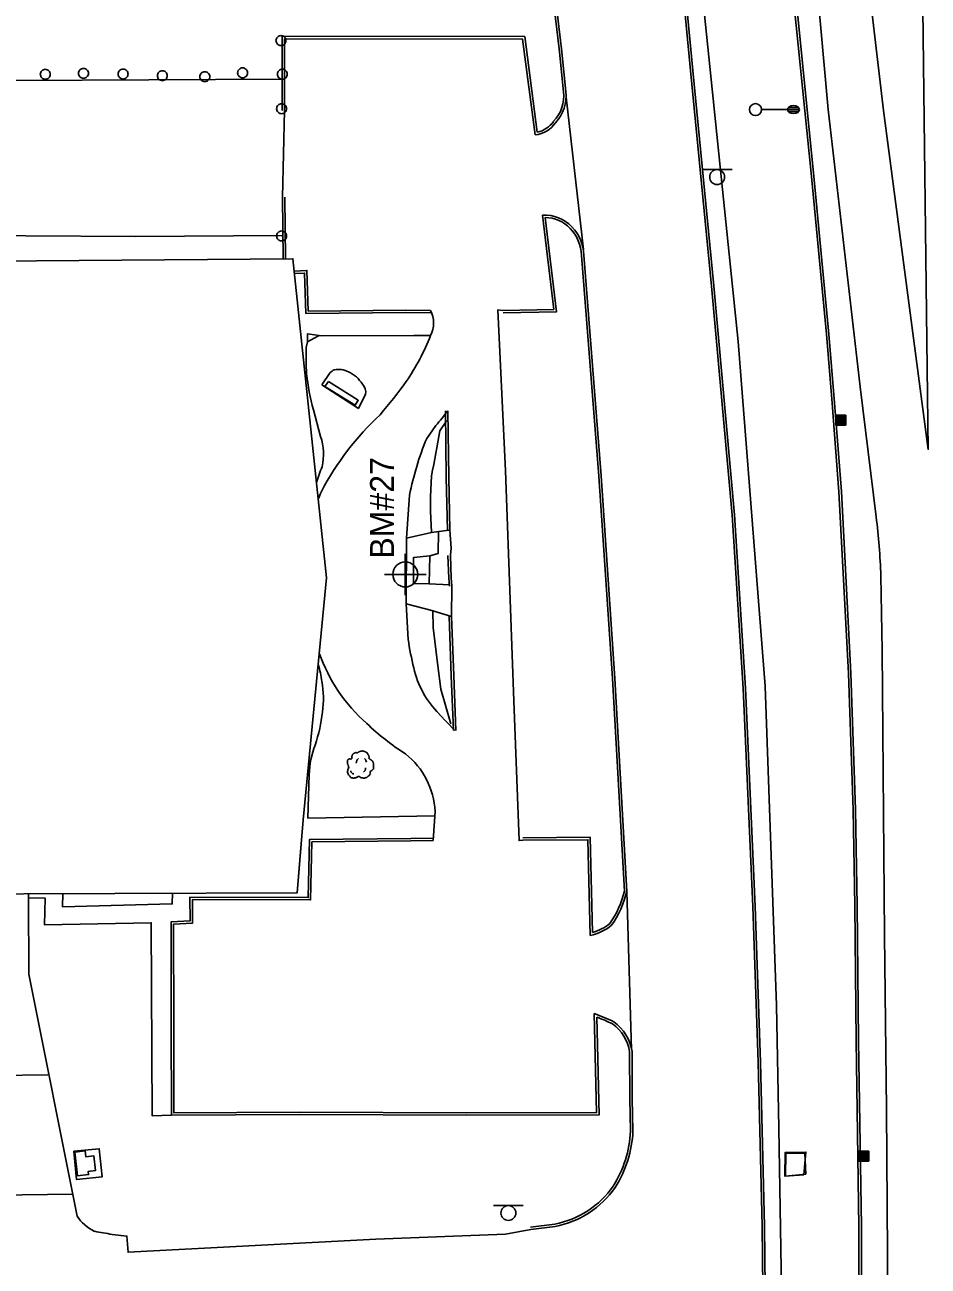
# Model space of a CAD drawing. Extents: x 2145380 to 2156929, y 139568 to 149130.
# Drawn here: x 2150561.8 to 2150788.1, y 141665.9 to 141976.9 of the extents above; entities that cross this region are included whole.
import ezdxf

# ---------------------------------------------------------------- set-up
doc = ezdxf.new("R2010")
doc.units = 0
for name, color, linetype in [('SURV_Benchmark', 7, 'Continuous'), ('SURV_Text', 7, 'Continuous'), ('TOPO_Asphalt', 7, 'Continuous'), ('TOPO_Building', 7, 'Continuous'), ('TOPO_Concrete', 7, 'Continuous'), ('TOPO_Curb Back', 7, 'Continuous'), ('TOPO_DRAIN_Manhole', 7, 'Continuous'), ('TOPO_Fence', 7, 'Continuous'), ('TOPO_Flowline', 7, 'Continuous'), ('TOPO_Light Pole', 7, 'Continuous'), ('TOPO_Misc', 7, 'Continuous'), ('TOPO_Misc Line', 7, 'Continuous'), ('TOPO_Sidewalk', 7, 'Continuous'), ('TOPO_Sign', 7, 'Continuous'), ('TOPO_Tree', 7, 'Continuous'), ('TOPO_Wall Freestanding', 7, 'Continuous')]:
    doc.layers.add(name, color=color, linetype=linetype)

# ---------------------------------------------------------------- blocks, each defined once
blk = doc.blocks.new('POST')
at = {"layer": 'TOPO_Misc'}
for start, end in [(89.99996, 180.00004), (179.99996, 270.00004), (359.99996, 90.00004), (269.99996, 0.00004)]:
    blk.add_arc((-0.01, 0.03), 3.16, start, end, dxfattribs=at)
blk = doc.blocks.new('CB')
at = {"layer": 'TOPO_Misc'}
for p, q in [((-3.08, 2.99), (3.24, 2.99)), ((-3.08, 2.68), (3.24, 2.68)), ((-3.08, 2.36), (3.24, 2.36)), ((-3.08, 2.05), (3.24, 2.05)), ((-3.08, 1.73), (3.24, 1.73)), ((-3.08, 1.4), (3.24, 1.4)), ((-3.08, 1.1), (3.24, 1.1)), ((-3.08, 0.77), (3.24, 0.77)), ((-3.08, 0.46), (3.24, 0.46)), ((-3.08, 0.14), (3.24, 0.14)), ((-3.08, -0.17), (3.24, -0.17)), ((-3.08, -0.48), (3.24, -0.48)), ((-3.08, -0.8), (3.24, -0.8)), ((-3.08, -1.11), (3.26, -1.11)), ((-3.08, -1.43), (3.26, -1.43)), ((-3.08, -1.75), (3.26, -1.75)), ((-3.08, -2.07), (3.26, -2.07)), ((-3.08, -2.39), (3.26, -2.39)), ((-3.08, -2.7), (3.26, -2.7)), ((-3.08, -3.02), (3.26, -3.02))]:
    blk.add_line(p, q, dxfattribs=at)
blk.add_lwpolyline([(3.26, -3.29), (3.24, 3.05), (-3.09, 3.04), (-3.08, -3.3), (3.26, -3.29)], dxfattribs=at)
blk = doc.blocks.new('LP')
at = {"layer": 'TOPO_Light Pole'}
blk.add_line((3.81, 0), (20.32, 0), dxfattribs=at)
for points in [[(20.32, 0), (27.94, 0)], [(20.32, 0), (23.5, 0)], [(20.83, 1.27), (27.43, 1.27)], [(20.83, 1.27), (23.5, 1.27)], [(23.71, 1.27), (27.43, 1.27)], [(23.71, 0), (27.94, 0)], [(20.83, -1.27), (27.43, -1.27)], [(20.83, -1.27), (23.5, -1.27)], [(23.71, -1.27), (27.43, -1.27)]]:
    blk.add_lwpolyline(points, dxfattribs=at)
blk.add_circle((0, 0), 3.81, dxfattribs=at)
blk.add_ellipse((24.13, 0), major_axis=(3.81, 0), ratio=0.666667, dxfattribs=at)
blk = doc.blocks.new('TREE')
at = {"layer": 'TOPO_Tree'}
for points in [[(-14.1, -0.4), (-14.2, 0.5), (-14.4, 1.4), (-14.6, 2.3), (-14.8, 3.2), (-15.5, 4), (-15.7, 4.9), (-15.8, 5.6), (-15.7, 6.3), (-15.7, 7), (-15.6, 7.9), (-15.7, 8.8), (-15.1, 9.7), (-14.6, 10.4), (-13.8, 10.5), (-13, 10.7), (-12.2, 11), (-11.1, 10), (-10.4, 10.7), (-9.4, 11.7), (-10.3, 13.3), (-9.8, 14.4), (-9.6, 15.1), (-9.3, 15.9), (-8.8, 16.5), (-8.2, 17.3), (-7.5, 17.7), (-6.7, 18.1), (-6.1, 18.4), (-5.6, 18.6), (-5.1, 18.7), (-4.5, 18.7), (-4, 18.5), (-3.5, 18.1)], [(-3.5, 17.6), (-3.1, 18.3), (-2.6, 18.8), (-1.9, 19.2), (-1, 19.7), (-0.2, 20), (0.7, 20.2), (1.6, 20.5), (2.5, 20.8), (3.4, 20.8), (4.1, 20.7), (4.8, 20.5), (5.5, 20.2), (6.4, 19.9), (7.3, 19.7), (8.2, 19.2), (9.4, 18.4), (10, 17.2), (10.8, 16), (11.2, 15.3), (11.6, 14.6), (11.9, 13.9), (12.2, 13.1), (11.4, 12), (11.9, 11.2), (12, 11), (12.2, 10.9), (12.4, 10.7), (12.9, 10.4), (13.5, 10), (14, 9.7), (14.7, 9.2), (15.4, 8.7), (16.1, 8.1), (16.7, 7.5), (16.9, 6.7), (17.1, 6), (17.6, 4.4), (17.7, 2.8), (17.7, 1.2), (17.7, -0.2), (17.8, -2.2), (16.6, -3), (15.5, -3.8), (14.3, -4.6), (13.2, -5.3)], [(13.2, -5.3), (13.3, -5.8), (13.4, -6.3), (13.4, -6.7), (13.8, -8.5), (12.2, -10), (10.8, -11.5), (10, -12.3), (9.1, -12.8), (8.2, -13.1), (6, -13.8), (3.3, -13.6), (1.3, -13.1), (0.5, -12.9), (-0.1, -11.4), (-0.8, -11.5), (-2, -11.6), (-3.3, -12.8), (-4.5, -13.1), (-6.1, -13.5), (-7.8, -14), (-9.3, -13.6), (-11.4, -13.1), (-12.8, -11.4), (-14.1, -9.4), (-15.3, -7.3), (-15.6, -5.1), (-15.1, -3), (-14.9, -1.9), (-13.9, -0.8), (-13.5, 0.1)], [(-4.2, 5.1), (-4.5, 6.1), (-4.3, 7.2), (-3.8, 8.2), (-3.3, 9.3), (-2.7, 10.3), (-1.6, 11)], [(5.9, 11.2), (6.5, 10.7), (7, 10.2), (7.4, 9.5), (7.9, 8.6), (8.3, 7.6), (8.5, 6.6)], [(-11.4, -4.5), (-11.5, -5.4), (-11, -6.3), (-10.1, -7.2), (-9.3, -8), (-8.5, -8.3), (-7.7, -8.1)], [(4.8, -6.3), (5.7, -5.7), (6.3, -4.9), (6.8, -3.9), (7.4, -2.8), (7.6, -1.7), (7.5, -0.6)]]:
    blk.add_open_spline(points, degree=3, dxfattribs=at)
blk = doc.blocks.new('BM')
at = {"layer": 'SURV_Benchmark'}
for p, q in [((0, 2.49), (0, 4.15)), ((-2.49, 0), (-4.16, 0)), ((4.16, 0), (2.49, 0)), ((0, -4.16), (0, -2.49))]:
    blk.add_line(p, q, dxfattribs=at)
for points in [[(0, 2.49), (0, 2.49), (0, 0), (2.49, 0), (2.49, 0), (2.49, 0)], [(0, 2.49), (0, 2.49), (0, 0), (2.49, 0), (2.49, 0), (2.49, 0), (2.49, 0)], [(-2.5, 0), (-2.49, 0), (0, 0), (0, -2.49), (0, -2.49)], [(-2.5, 0), (-2.49, 0), (0, 0), (0, -2.49), (0, -2.49)]]:
    blk.add_lwpolyline(points, dxfattribs=at)
for start, end in [(90.0638, 180.0068), (0.0638, 90.0068), (0.0638, 90.0068), (180.0638, 270.0068), (180.0638, 270.0068), (269.9472, 359.9927)]:
    blk.add_arc((0, 0), 2.5, start, end, dxfattribs=at)

msp = doc.modelspace()

# ---------------------------------------------------------------- linework, layer by layer
at = {"layer": 'TOPO_Asphalt'}
for p, q in [((2150701.7, 141920.59), (2150697.39, 141958.77)), ((2150626.34, 141933.73), (2150626.88, 141955.42)), ((2150668.68, 141828.57), (2150668.77, 141836.28)), ((2150713.8, 141720.23), (2150712.59, 141759.83)), ((2150573.84, 141683.97), (2150543.68, 141683.53))]:
    msp.add_line(p, q, dxfattribs=at)
for points in [[(2150784.22, 142321.18), (2150785.51, 142174.58), (2150786.21, 142060.54), (2150786.7, 141980.91), (2150787.83, 141890.92), (2150788.07, 141870.55), (2150776.91, 141955.43), (2150769.94, 142014.37), (2150769.64, 142016.94), (2150769.78, 142050.34), (2150769.37, 142062.64), (2150768.99, 142106.08), (2150768.6, 142191.81), (2150767.48, 142307.96)], [(2150775.04, 141853.65), (2150771.01, 141886.23), (2150762.99, 141955.69), (2150759.17, 141998.33), (2150755.55, 142020.63)], [(2150626.27, 141963.32), (2150559.5, 141962.96), (2150488.73, 141962.45), (2150479.24, 141962.33)], [(2150686.56, 141772.63), (2150685.62, 141772.54), (2150684.26, 141807.59), (2150682.22, 141865.21), (2150680.3, 141905.46), (2150681.57, 141905.37)], [(2150662.47, 141873.26), (2150664.77, 141876.51)], [(2150657.82, 141822.95), (2150657.36, 141831.85), (2150657.39, 141848.34), (2150658.17, 141859.11)], [(2150668.39, 141844.02), (2150668.63, 141845.8), (2150668.27, 141850.3)], [(2150754.12, 140985.36), (2150761.18, 141045.16), (2150767.3, 141118.3), (2150773.72, 141195.47), (2150779.3, 141269.82), (2150781.13, 141293.61), (2150780.7, 141357.79), (2150779.84, 141451.99), (2150779.07, 141536.53), (2150778.24, 141620.87), (2150777.64, 141705.29), (2150777.09, 141748.87), (2150776.58, 141820.16), (2150776.24, 141838.85)], [(2150669.48, 141800.11), (2150665.6, 141804.25)], [(2150664.56, 141779.85), (2150664.09, 141772.56)], [(2150583.67, 141673.9), (2150587.37, 141673.47), (2150587.68, 141669.42), (2150649.69, 141672.66), (2150682.21, 141673.95), (2150688.57, 141675.14)]]:
    msp.add_lwpolyline(points, dxfattribs=at)
for centre, radius, start, end in [((2150657.36, 141902.16), 6.82, 332.9628, 27.7838), ((2150606.79, 141921.5), 60.93, 326.0936, 338.3883), ((2150515.1, 141993.36), 177.32, 319.9381, 323.3492), ((2150699.13, 141827.05), 71.12, 132.797, 152.411), ((2150612.55, 141921.55), 68.96, 319.223, 323.1994), ((2150731.31, 141844.65), 74.55, 157.434, 168.8197), ((2150700.07, 141832.12), 69.78, 156.4643, 158.1438), ((2150592.67, 141831.49), 183.71, 2.297, 6.9274), ((2150733.88, 141834.22), 76.89, 188.4258, 193.8705), ((2150675.21, 141833.48), 42.06, 199.4563, 228.712), ((2150682.15, 141820.92), 23.48, 192.6406, 225.2177), ((2150691.99, 141848.44), 64.42, 226.2748, 237.2768), ((2150645.03, 141778.91), 19.55, 2.7398, 51.6264), ((2150583.94, 141684.33), 10.75, 212.8764, 244.2022), ((2150602.21, 141794.88), 122.39, 259.1945, 261.2879)]:
    msp.add_arc(centre, radius, start, end, dxfattribs=at)
at = {"layer": 'TOPO_Building'}
msp.add_lwpolyline([(2150414.75, 141916.64), (2150628.96, 141918.31), (2150637.38, 141838.37), (2150631.52, 141777.75), (2150630, 141759.43), (2150492.94, 141758.99), (2150492.91, 141755), (2150478.69, 141755.12), (2150478.72, 141759), (2150415.44, 141758.64), (2150415.72, 141792.35)], close=True, dxfattribs=at)
msp.add_lwpolyline([(2150478.58, 141759), (2150478.68, 141754.67), (2150493.03, 141755), (2150492.94, 141758.99), (2150630, 141759.43), (2150631.02, 141771.72)], dxfattribs=at)
at = {"layer": 'TOPO_Concrete'}
for points in [[(2150574.06, 141694.7), (2150580.43, 141695.35), (2150581.15, 141688.27), (2150574.78, 141687.63), (2150574.06, 141694.7)], [(2150756.95, 141688.82), (2150752.14, 141688.5), (2150752.24, 141694.4), (2150757.43, 141694.51), (2150756.95, 141688.82)]]:
    msp.add_lwpolyline(points, dxfattribs=at)
at = {"layer": 'TOPO_Curb Back'}
for p, q in [((2150626.34, 141933.73), (2150626.49, 141918.29)), ((2150626.94, 141933.73), (2150627.09, 141918.29))]:
    msp.add_line(p, q, dxfattribs=at)
for points in [[(2150665.92, 142234.23), (2150672.82, 142175.43), (2150683.05, 142079.24), (2150687.74, 142036.69), (2150695.66, 141970.85), (2150696.74, 141960.14)], [(2150666.52, 142234.29), (2150673.41, 142175.5), (2150683.64, 142079.3), (2150688.34, 142036.76), (2150696.26, 141970.91), (2150697.33, 141960.21)], [(2150745.49, 141717), (2150744.14, 141756.02), (2150741.71, 141810.65), (2150738.98, 141854.07), (2150733.82, 141911.47), (2150728.53, 141965.42), (2150722.71, 142026.7), (2150719.84, 142047.27)], [(2150746.09, 141717.02), (2150744.74, 141756.04), (2150742.31, 141810.69), (2150739.58, 141854.11), (2150734.42, 141911.53), (2150729.12, 141965.48), (2150723.31, 142026.77), (2150720.44, 142047.36)], [(2150752.87, 141998.18), (2150758.72, 141939.77), (2150762.6, 141899.37), (2150764.01, 141882.16), (2150765.73, 141859.91), (2150768.07, 141814.42), (2150769.27, 141780.28), (2150769.69, 141756.26), (2150770.02, 141722.4)], [(2150753.47, 141998.26), (2150759.31, 141939.83), (2150763.19, 141899.43), (2150764.61, 141882.21), (2150766.33, 141859.95), (2150768.67, 141814.45), (2150769.87, 141780.29), (2150770.29, 141756.27), (2150770.62, 141722.4)], [(2150690.16, 141950.01), (2150687.02, 141973.94), (2150626.27, 141974.02), (2150626.28, 141955.42)], [(2150689.65, 141949.31), (2150686.49, 141973.34), (2150626.87, 141973.42), (2150626.88, 141955.42)], [(2150681.57, 141905.37), (2150694.3, 141905.61), (2150691.47, 141929.18)], [(2150681.58, 141904.77), (2150694.98, 141905.03), (2150692.14, 141928.6)], [(2150701.25, 141919.15), (2150705.59, 141863.84), (2150709.02, 141813.11), (2150711.98, 141759.88)], [(2150701.85, 141919.19), (2150706.19, 141863.88), (2150709.62, 141813.15), (2150712.59, 141759.83)], [(2150629.29, 141915.18), (2150632.45, 141915.36), (2150632.78, 141905.18), (2150657.22, 141905.45), (2150663.4, 141905.34)], [(2150629.36, 141914.58), (2150631.87, 141914.72), (2150632.2, 141904.57), (2150657.22, 141904.85), (2150663.39, 141904.74)], [(2150667.17, 141880.24), (2150667.38, 141863.52), (2150667.67, 141850.29)], [(2150667.77, 141880.24), (2150667.98, 141863.53), (2150668.27, 141850.3)], [(2150667.79, 141843.98), (2150668.03, 141838.31), (2150668.17, 141836.24)], [(2150668.39, 141844), (2150668.63, 141838.34), (2150668.77, 141836.28)], [(2150668.08, 141828.68), (2150668.62, 141813.84), (2150669.18, 141800.1)], [(2150668.68, 141828.71), (2150669.22, 141813.87), (2150669.78, 141800.12)], [(2150705.04, 141728.32), (2150705.63, 141703.81), (2150672.4, 141703.76), (2150630.6, 141703.95), (2150598.53, 141703.74), (2150598.49, 141726.43), (2150598.43, 141752.15), (2150603.21, 141752.43), (2150603.17, 141758.38), (2150632.79, 141758.28), (2150633.15, 141772.83), (2150658.45, 141773.04), (2150664.07, 141773.16)], [(2150704.42, 141729.19), (2150705.02, 141704.4), (2150672.4, 141704.36), (2150630.6, 141704.55), (2150599.13, 141704.34), (2150599.09, 141726.43), (2150599.03, 141751.58), (2150603.81, 141751.86), (2150603.78, 141757.78), (2150633.38, 141757.68), (2150633.73, 141772.23), (2150658.46, 141772.44), (2150664.09, 141772.56)], [(2150704.02, 141749.51), (2150703.41, 141773.37), (2150686.55, 141773.23)], [(2150703.44, 141748.73), (2150702.83, 141772.76), (2150686.56, 141772.63)], [(2150753.26, 140989.74), (2150751.22, 141016.02), (2150756.58, 141063.34), (2150763.5, 141134.07), (2150767.16, 141185.1), (2150769.58, 141229.72), (2150771.67, 141285.49), (2150772.73, 141343.53), (2150772.31, 141404.13), (2150771.67, 141471.4), (2150771.58, 141538.08), (2150770.95, 141603.47), (2150770.74, 141675.9), (2150770.02, 141722.4)], [(2150753.86, 140989.81), (2150751.82, 141016), (2150757.18, 141063.27), (2150764.1, 141134.02), (2150767.75, 141185.06), (2150770.18, 141229.69), (2150772.27, 141285.47), (2150773.33, 141343.52), (2150772.91, 141404.13), (2150772.27, 141471.41), (2150772.18, 141538.09), (2150771.55, 141603.47), (2150771.34, 141675.91), (2150770.62, 141722.41)], [(2150713.53, 141699.77), (2150713.36, 141707.94), (2150713.29, 141719.65)], [(2150714.13, 141699.76), (2150713.96, 141707.95), (2150713.89, 141719.7)], [(2150745.49, 141717), (2150746.46, 141675.95), (2150747.09, 141622), (2150747.52, 141558.34), (2150748.12, 141501.05), (2150748.91, 141441.03), (2150748.82, 141384.99)], [(2150746.09, 141717.02), (2150747.06, 141675.96), (2150747.69, 141622.01), (2150748.12, 141558.34), (2150748.72, 141501.06), (2150749.51, 141441.03), (2150749.42, 141385.01)], [(2150688.5, 141675.74), (2150694.53, 141676.48)], [(2150688.57, 141675.14), (2150694.62, 141675.89)]]:
    msp.add_lwpolyline(points, dxfattribs=at)
for centre, radius, start, end in [((2150687.51, 141959.12), 9.29, 316.4664, 6.3444), ((2150687.51, 141959.12), 9.89, 316.7344, 6.3262), ((2150688.79, 141956.49), 7.22, 276.8134, 324.9708), ((2150688.79, 141956.48), 6.62, 281.9482, 325.3452), ((2150692.14, 141920.13), 9.08, 42.849, 94.2095), ((2150692.14, 141920.13), 8.48, 42.7978, 89.9516), ((2150691.05, 141918.75), 10.22, 2.2809, 44.3259), ((2150691.05, 141918.75), 10.82, 2.3422, 44.2852), ((2150688.24, 141765.65), 24.43, 325.297, 346.3564), ((2150688.24, 141765.65), 25.03, 325.0877, 346.561), ((2150700.17, 141762.22), 13.88, 283.6304, 308.2693), ((2150700.17, 141762.22), 13.28, 286.8573, 307.8912), ((2150689.03, 141685.46), 46.36, 64.0551, 70.6085), ((2150689.04, 141685.48), 45.73, 64.1161, 69.5162), ((2150702.77, 141717.98), 10.66, 9.0116, 54.2136), ((2150702.77, 141717.98), 11.26, 8.7788, 54.4804), ((2150684.86, 141701.2), 28.7, 327.9943, 357.1326), ((2150684.86, 141701.2), 29.3, 327.9662, 357.1737), ((2150690.22, 141699.2), 23.12, 280.7352, 325.1646), ((2150690.22, 141699.2), 23.72, 280.6874, 325.2009)]:
    msp.add_arc(centre, radius, start, end, dxfattribs=at)
at = {"layer": 'TOPO_DRAIN_Manhole'}
msp.add_lwpolyline([(2150757.41, 141688.97), (2150752.35, 141688.45), (2150752.44, 141694.18), (2150757.21, 141694.23)], close=True, dxfattribs=at)
at = {"layer": 'TOPO_Fence'}
msp.add_lwpolyline([(2150636.94, 142436.49), (2150647.11, 142421.59), (2150659.49, 142398.34), (2150673.51, 142369.32), (2150675.45, 142362.72), (2150676.65, 142359.21), (2150678.55, 142353.1), (2150687.41, 142327.83), (2150694.35, 142298.57), (2150699.37, 142270.94), (2150700.68, 142261.68), (2150704.55, 142228.45), (2150715, 142136), (2150724.1, 142059.32), (2150731.74, 141982.66), (2150740.47, 141897.53), (2150747.25, 141811.22), (2150750.08, 141731.24), (2150750.69, 141700.48), (2150751.7, 141640.19)], dxfattribs=at)
at = {"layer": 'TOPO_Flowline'}
msp.add_lwpolyline([(2150567.53, 141713.88), (2150541.92, 141713.49), (2150509.16, 141713.09), (2150466.33, 141713.31), (2150432.28, 141713.86), (2150416.8, 141714.12), (2150409.15, 141715.25), (2150397.63, 141718.93), (2150381.89, 141724.6), (2150374.31, 141727.84), (2150368.87, 141731.89), (2150364.57, 141736.5), (2150362, 141740.07), (2150352.2, 141752.66), (2150343.64, 141760.25), (2150336.95, 141766.5), (2150331.04, 141772.47), (2150324.59, 141777.76), (2150319.65, 141782.69), (2150316.58, 141785.5)], dxfattribs=at)
at = {"layer": 'TOPO_Misc Line'}
msp.add_lwpolyline([(2150574.33, 141694.53), (2150575.03, 141688.54), (2150577.78, 141688.86), (2150577.69, 141689.66), (2150579.5, 141689.87), (2150579.06, 141693.58), (2150577.05, 141693.34), (2150576.88, 141694.83), (2150574.33, 141694.53)], dxfattribs=at)
at = {"layer": 'TOPO_Sidewalk'}
msp.add_line((2150562.7, 141758.14), (2150562.72, 141759.21), dxfattribs=at)
for points in [[(2150632.27, 141896.06), (2150632.63, 141897.46), (2150632.58, 141899.46), (2150636.1, 141899)], [(2150635.89, 141873.75), (2150634.09, 141880.45)], [(2150664.48, 141778.72), (2150632.72, 141778.2), (2150633.02, 141789.1)], [(2150566.89, 141758.16), (2150566.72, 141751.44), (2150593.49, 141751.96), (2150593.74, 141703.58), (2150598.53, 141703.74)], [(2150598.77, 141759.33), (2150598.74, 141756.69), (2150571.26, 141755.91), (2150571.29, 141759.24)]]:
    msp.add_lwpolyline(points, dxfattribs=at)
for centre, radius, start, end in [((2150800.68, 141895.08), 168.42, 179.6662, 181.9052), ((2150691.99, 141896.25), 60.02, 186.4775, 195.2673), ((2150622.65, 141869.29), 13.97, 347.2689, 18.6244), ((2150671.47, 141851.44), 38.16, 157.2384, 163.569), ((2150603.46, 141807.51), 33.12, 8.4805, 16.0485), ((2150611.66, 141808.1), 24.93, 352.3366, 9.9105), ((2150596.91, 141809.32), 39.72, 341.1513, 353.4257), ((2150657.34, 141788.1), 24.33, 159.8394, 177.649)]:
    msp.add_arc(centre, radius, start, end, dxfattribs=at)
at = {"layer": 'TOPO_Sign'}
for points in [[(2150731.46, 141940.63), (2150738.95, 141940.63)], [(2150735.21, 141940.63), (2150735.21, 141940.63)], [(2150733.34, 141938.76), (2150733.34, 141938.76)], [(2150735.21, 141936.89), (2150735.21, 141936.89)], [(2150737.07, 141938.76), (2150737.07, 141938.76)], [(2150679.17, 141681.12), (2150686.66, 141681.12)], [(2150681.05, 141679.25), (2150681.05, 141679.25)], [(2150682.92, 141681.11), (2150682.92, 141681.11)], [(2150684.78, 141679.25), (2150684.78, 141679.25)], [(2150682.92, 141677.38), (2150682.92, 141677.38)]]:
    msp.add_lwpolyline(points, dxfattribs=at)
msp.add_lwpolyline([(2150637.85, 141887.58), (2150645.33, 141882.87), (2150644.52, 141881.6), (2150636.98, 141886.28)], close=True, dxfattribs=at)
for centre, start, end in [((2150735.21, 141938.76), 90, 180), ((2150735.21, 141938.76), 360, 90), ((2150735.21, 141938.76), 180, 270), ((2150735.21, 141938.76), 270, 0), ((2150682.92, 141679.25), 90, 180), ((2150682.92, 141679.25), 180, 270), ((2150682.92, 141679.25), 360, 90), ((2150682.92, 141679.25), 270, 0)]:
    msp.add_arc(centre, 1.87, start, end, dxfattribs=at)
at = {"layer": 'TOPO_Wall Freestanding'}
for p, q in [((2150589.51, 141923.87), (2150626.35, 141924.13)), ((2150638.27, 141889.77), (2150636.21, 141886.7)), ((2150636.21, 141886.7), (2150645.39, 141880.79)), ((2150645.39, 141880.79), (2150647.16, 141884.35)), ((2150667.97, 141850.3), (2150663.68, 141849.76)), ((2150664.05, 141830.08), (2150657.36, 141831.85))]:
    msp.add_line(p, q, dxfattribs=at)
for points in [[(2150529.52, 141917.53), (2150529.33, 141918.71), (2150534.48, 141924.23), (2150589.51, 141923.87)], [(2150632.63, 141897.46), (2150635.34, 141899), (2150659.23, 141899.08), (2150663.44, 141899.06)], [(2150665.77, 141875.17), (2150667.5, 141877.79)], [(2150657.39, 141848.34), (2150663.68, 141849.76)], [(2150665.43, 141849.98), (2150665.33, 141844.44), (2150663.28, 141843.86), (2150663.04, 141836.87), (2150668.14, 141836.61)], [(2150663.28, 141843.86), (2150659.18, 141843.47), (2150659.16, 141836.96), (2150663.04, 141836.87)], [(2150668.68, 141828.71), (2150664.04, 141830.08), (2150664.1, 141825.92), (2150665.24, 141816.28), (2150665.99, 141810.47), (2150668.53, 141801.83)], [(2150574.93, 141678.48), (2150562.79, 141739.12), (2150562.7, 141758.13), (2150566.88, 141758.17)]]:
    msp.add_lwpolyline(points, dxfattribs=at)
for centre, radius, start, end in [((2150640.9, 141887.12), 3.73, 115.1279, 134.826), ((2150640.28, 141884.99), 5.6, 62.6639, 99.8974), ((2150640.01, 141883.26), 7.28, 29.5261, 67.0762), ((2150644.2, 141884.77), 2.99, 352.0402, 44.1158), ((2150253.38, 141946.62), 418.54, 348.6083, 350.1712), ((2150767.41, 141856.97), 103.98, 176.1506, 183.9732)]:
    msp.add_arc(centre, radius, start, end, dxfattribs=at)

# ---------------------------------------------------------------- block references
at = {"layer": 'SURV_Benchmark', "xscale": 1.25, "yscale": 1.25}
msp.add_blockref('BM', (2150657.09, 141839.21), dxfattribs=at)
at = {"layer": 'TOPO_Light Pole', "xscale": 0.39370000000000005, "yscale": 0.3937000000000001}
msp.add_blockref('LP', (2150744.82, 141955.65), dxfattribs=at)
at = {"layer": 'TOPO_Misc', "xscale": 0.39370000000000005, "yscale": 0.3937000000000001}
for name, p in [('POST', (2150625.96, 141972.94)), ('POST', (2150566.93, 141964.5)), ('POST', (2150576.5, 141964.73)), ('POST', (2150586.43, 141964.55)), ('POST', (2150596.26, 141964.15)), ('POST', (2150606.89, 141963.89)), ('POST', (2150616.35, 141964.85)), ('POST', (2150626.31, 141964.52)), ('POST', (2150626.12, 141955.86)), ('POST', (2150626.11, 141924)), ('CB', (2150766.16, 141877.91)), ('CB', (2150771.92, 141693.54))]:
    msp.add_blockref(name, p, dxfattribs=at)
at = {"layer": 'TOPO_Tree', "xscale": 0.19685000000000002, "yscale": 0.19685000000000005}
msp.add_blockref('TREE', (2150645.69, 141790.9), dxfattribs=at)

# ---------------------------------------------------------------- texts
at = {"layer": 'SURV_Text'}
msp.add_text('BM#27', height=6, rotation=90, dxfattribs=at).set_placement((2150654.27, 141843.18))

doc.saveas('drawing.dxf')
